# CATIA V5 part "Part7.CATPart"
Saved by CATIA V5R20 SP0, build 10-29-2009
Part number: 3JT12.5X2.5X17.5
Revision: ANY
Definition: UNKNOWN
Nomenclature: 3JT12.5X2.5X17.5
Source: Unknown
Bounding box of the stored display mesh (mm): x -8.75 to 8.75, y -1.25 to 1.25, z -8.75 to 8.75
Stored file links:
  C:\Users\Utente\Desktop\IO LAVORO\3D X SITO CF\CUMSA\3D files PW\pw101830\pw101830_injection\Part7.CATPart
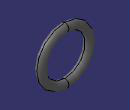
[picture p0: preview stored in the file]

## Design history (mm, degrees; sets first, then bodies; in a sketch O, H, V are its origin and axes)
Body1 "Revolución1" (main body)
  Solid1: solid without history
